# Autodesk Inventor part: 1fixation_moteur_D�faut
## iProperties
Created: 2011-01
Part Number: 1fixation_moteur_D�faut
Document SubType Name: Modeling
Designer: eric
Density: 1 g/cm^3
Mass: 21.7424 g
Surface Area: 188.248 cm^2
Volume: 21.7424 cm^3
Author: eric
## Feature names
1. Base1
